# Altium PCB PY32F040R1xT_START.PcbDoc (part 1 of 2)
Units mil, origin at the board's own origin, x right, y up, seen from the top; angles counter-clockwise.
Board outline 1771.65 x 3925.12 mil, 2 copper layers (Top Layer, Bottom Layer), stack 21 mil thick; 156 components, 167 nets, 616 pads, 288 vias.
Unrouted connection lines stored in the file: 5.
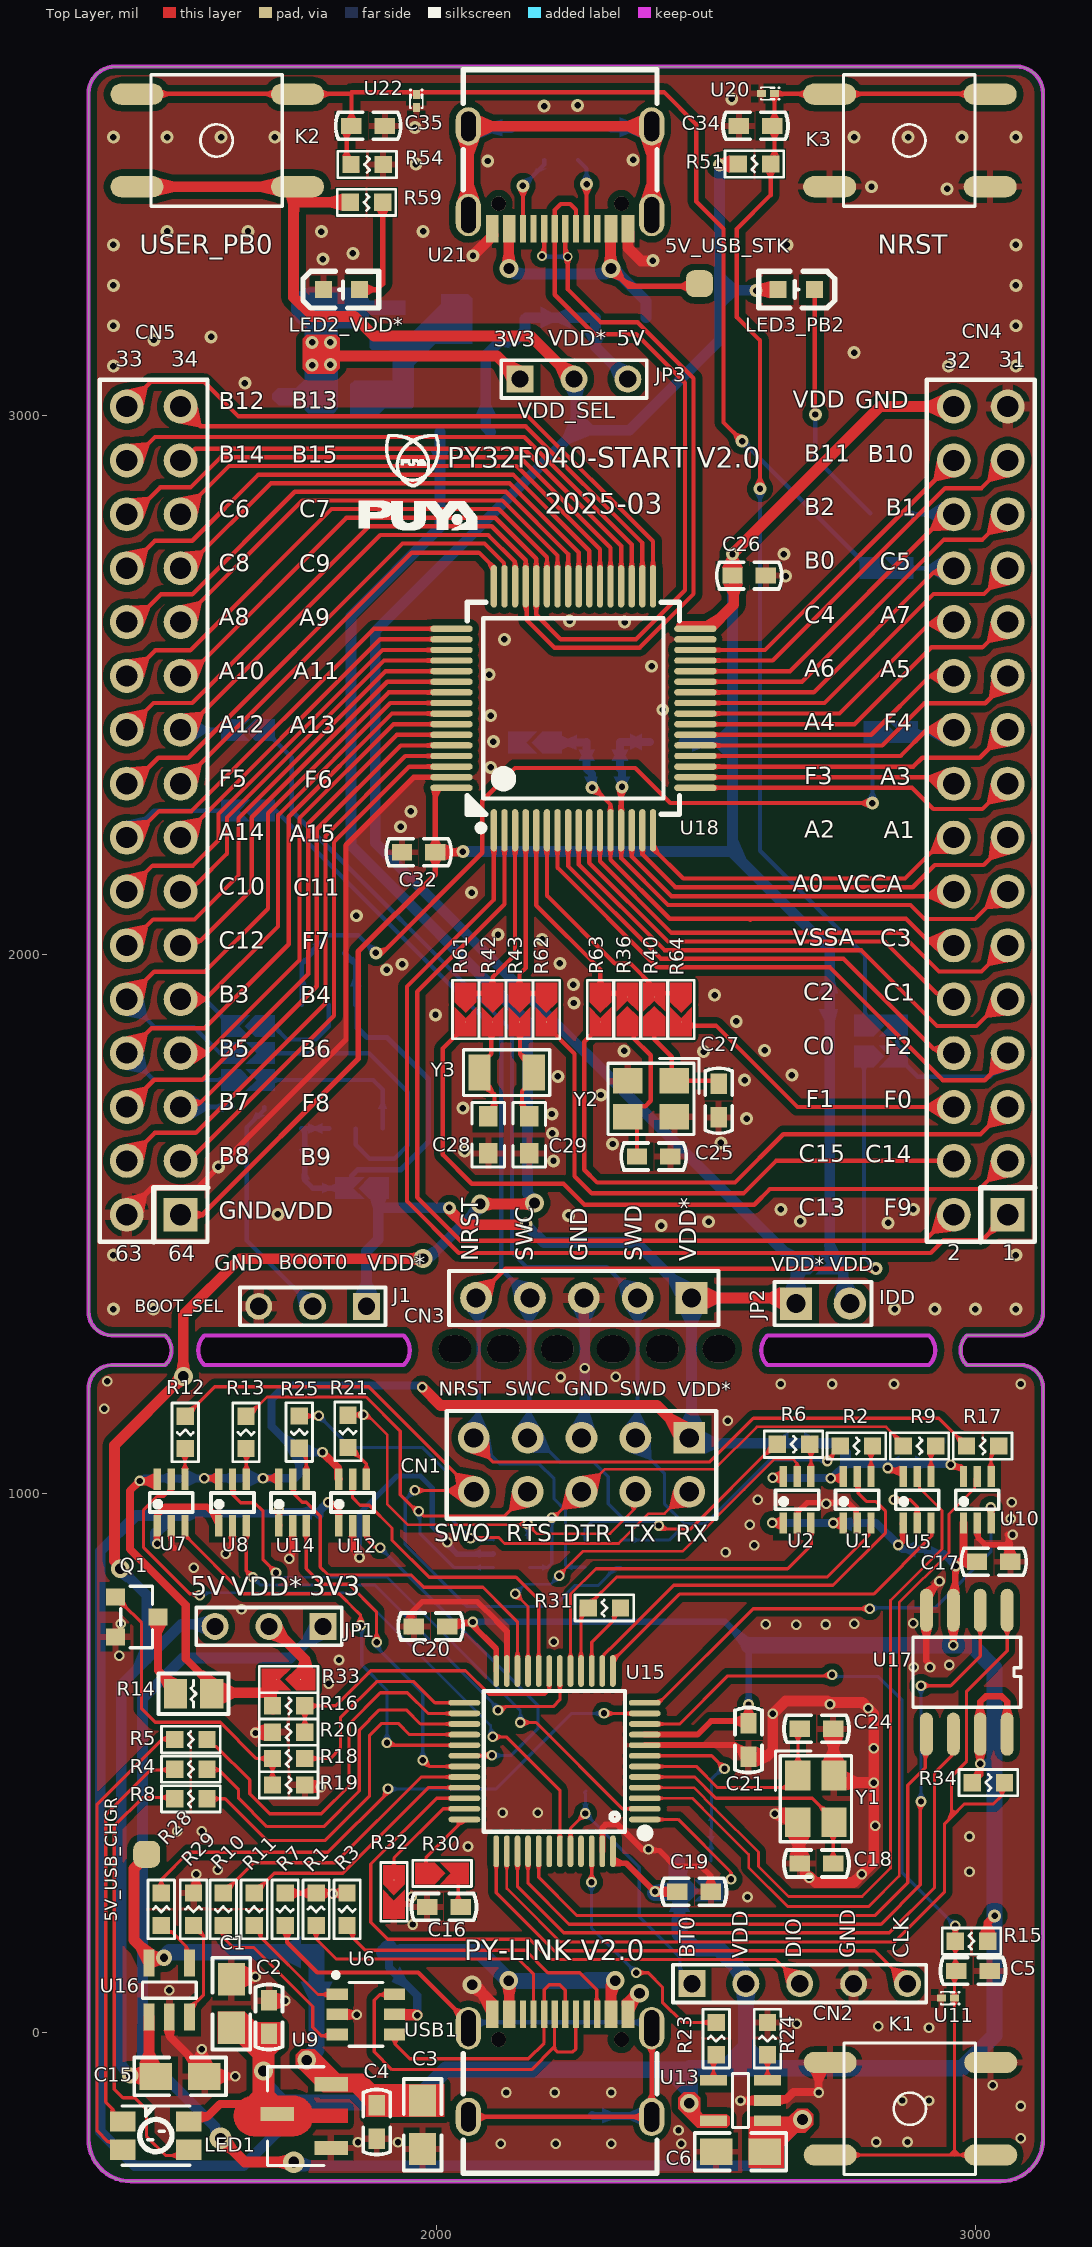
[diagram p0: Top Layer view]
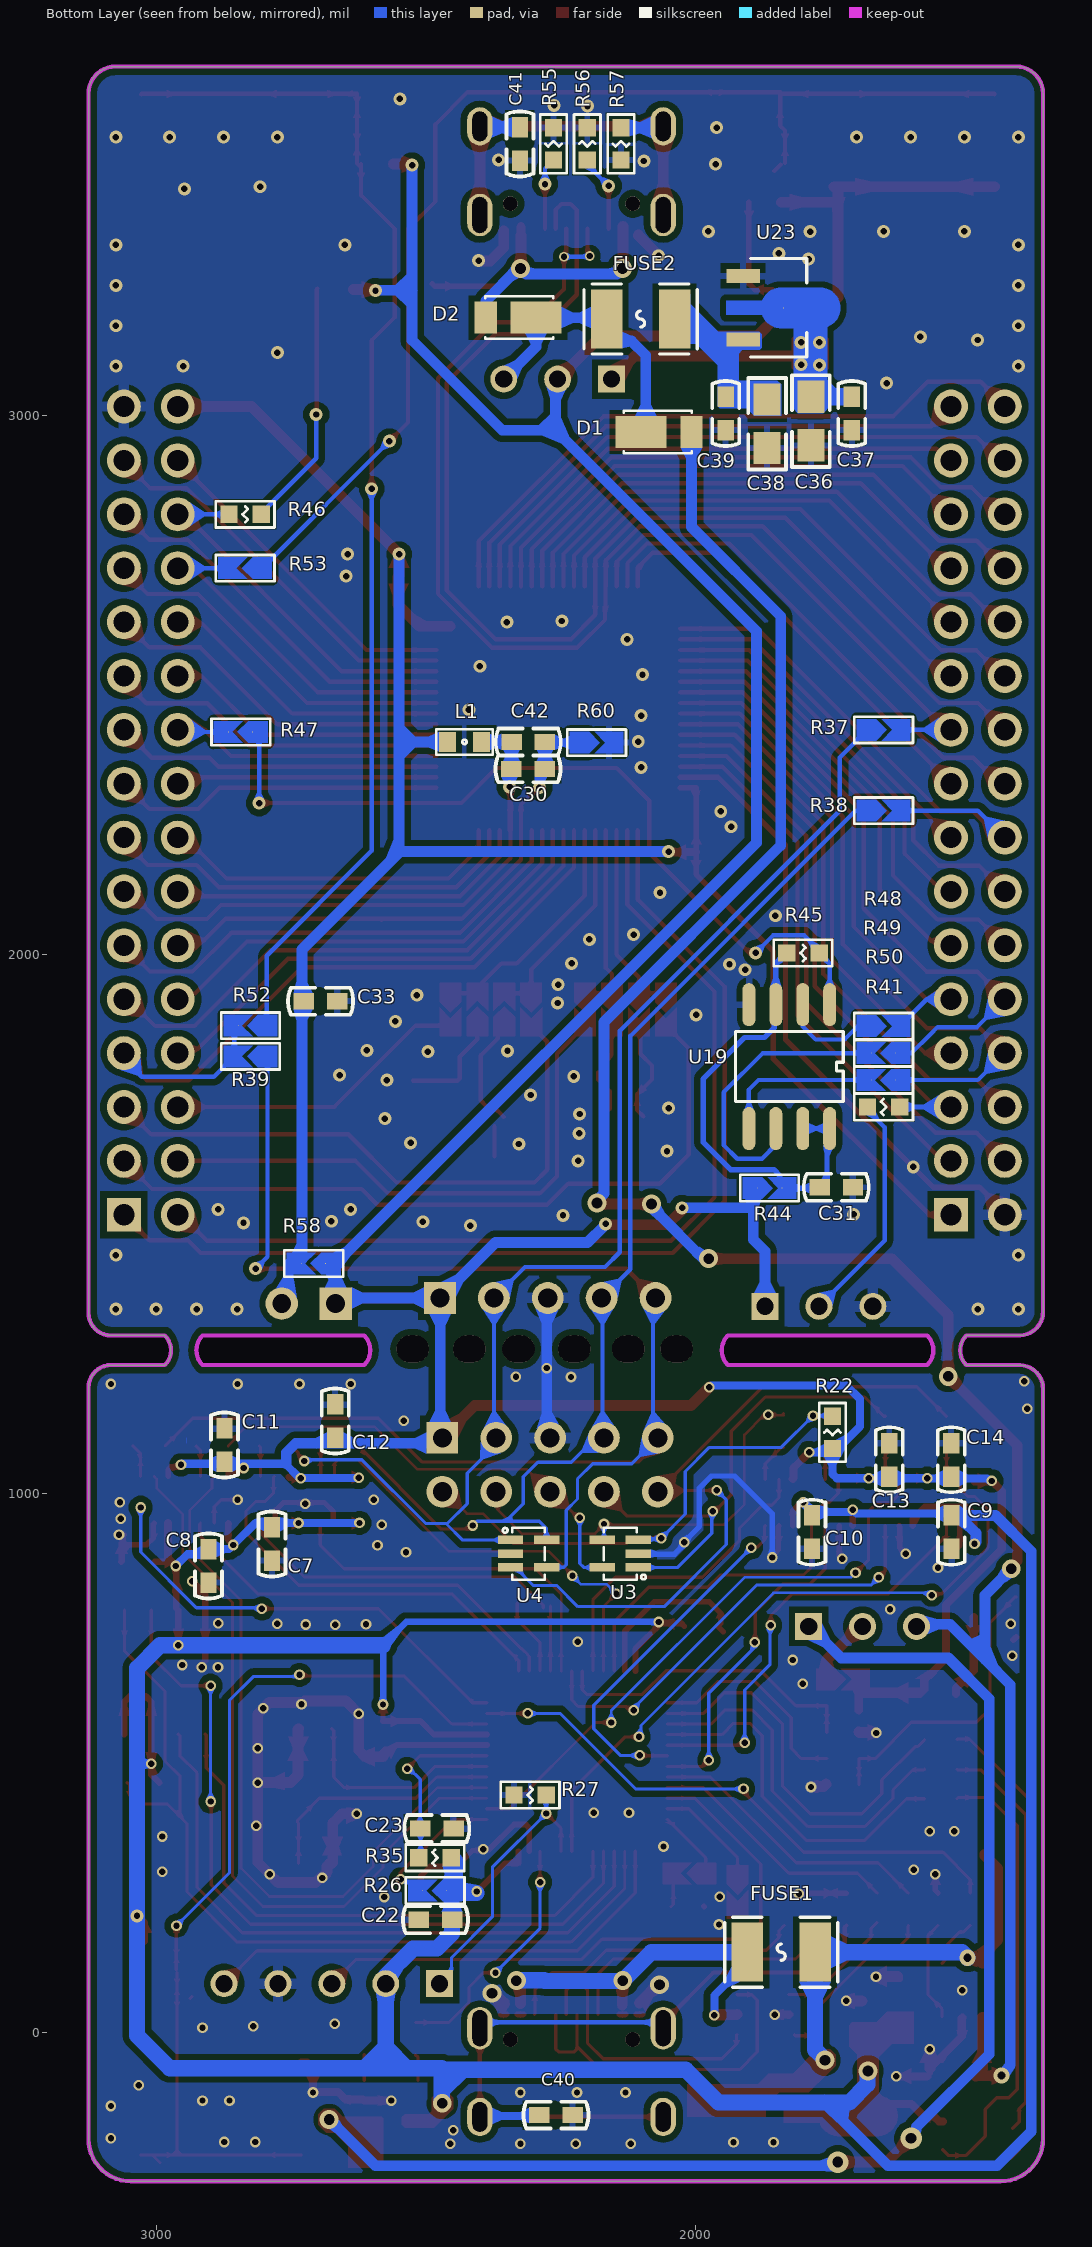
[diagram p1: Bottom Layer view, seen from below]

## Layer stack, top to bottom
Top Solder: solder mask 0.4, Solder Resist, Dk 3.5
Top Layer: signal copper 1.4
Dielectric 2: prepreg 2.8, Composite dielectric, Dk 4.1
Dielectric 1: prepreg 12.6, Composite dielectric, Dk 4.1
Dielectric 3: prepreg 2.8, Composite dielectric, Dk 4.1
Bottom Layer: signal copper 1.4
Bottom Solder: solder mask 0.4, Solder Resist, Dk 3.5

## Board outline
1354,-198.26 1354,1193 cw(c1397.75,1194.25) 1396.5,1238 1496.5,1238 ccw(c1469,1265.5) 1496.5,1293 1396.5,1293 cw(c1397.75,1336.75) 1354,1338 1354,3598.12 cw(c1404,3598.12) 1404,3648.12 3075.65,3648.12 cw(c3075.65,3598.12) 3125.65,3598.12 3125.65,1334.65 cw(c3084,1334.65) 3084,1293 2984,1293 ccw(c3011.5,1265.5) 2984,1238 3084,1238 cw(c3084,1196.35) 3125.65,1196.35 3125.65,-198.26 cw(c3046.91,-198.26) 3046.91,-277 1432.74,-277 cw(c1432.74,-198.26)
cut-out: 2614,1238 cw(c2641.5,1265.5) 2614,1293 2914,1293 cw(c2886.5,1265.5) 2914,1238
cut-out: 1569,1238 cw(c1596.5,1265.5) 1569,1293 1939,1293 cw(c1911.5,1265.5) 1939,1238
cut-out: 1569,1238 cw(c1596.5,1265.5) 1569,1293 1939,1293 cw(c1911.5,1265.5) 1939,1238 1919,1238
cut-out: 2614,1238 cw(c2641.5,1265.5) 2614,1293 2914,1293 cw(c2886.5,1265.5) 2914,1238

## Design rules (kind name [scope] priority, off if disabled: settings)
Clearance polygon [InPolygon] p1: gap=12 ignorepadtopadclearanceinfootprint=TRUE
Clearance [All] p2: gap=6 ignorepadtopadclearanceinfootprint=TRUE
HoleToHoleClearance [All] p1: gap=1 allowstackedmicrovias=TRUE
MinimumSolderMaskSliver [All] p1: minsoldermaskwidth=0
PlaneClearance [All] p1: clearance=8
PlaneConnect [All] p1: planeconnectstyle=Direct reliefexpansion=20 reliefentries=4 reliefconductorwidth=10 reliefairgap=10
PolygonConnect [All] p1: thpad.connectstyle=Relief thpad.reliefconductorwidth=20 thpad.reliefentries=4 thpad.polygonreliefangle="90 Angle" thpad.airgapwidth=10 smdpad.connectstyle=Relief smdpad.reliefconductorwidth=12 smdpad.reliefentries=4 smdpad.polygonreliefangle="90 Angle" smdpad.airgapwidth=10 via.connectstyle=Direct via.reliefconductorwidth=10 via.reliefentries=4 via.polygonreliefangle="90 Angle" via.airgapwidth=10
RoutingVias [All] p1: holewidth=28 width=50 viastyle="Through Hole" minholewidth=28 minwidth=50 maxholewidth=28 maxwidth=50
SilkToSilkClearance [All] p1: silktosilkclearance=0
SilkToSolderMaskClearance [IsPad] p1: minsilkscreentomaskgap=0 clearancetoexposedcopper=TRUE
SolderMaskExpansion [All] p1: expansion=4 istentingtop=FALSE
UnRoutedNet [All] p1: checkbadconnections=TRUE
Width [All] p1: maxlimit=100 minlimit=5 preferedwidth=8
23 further rules are at their usual default settings.

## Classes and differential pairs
component class PY32F040R1xT_START: 5V_USB_STK C25 C26 C27 C28 C29 C30 C31 C32 C33 C34 C35 C36 C37 C38 C39 C41 C42 CN3 CN4 CN5 D1 D2 FUSE2 "IDD Test" J1 JP2 JP3 K2 K3 L1 LED2_VDD* LED3_PB2 PF8 R36 R37 R38 R39 R40 R41 R42 R43 R44 R45 R46 R47 R48 R49 R50 R51 R52 R53 R54 R55 R56 R57 R58 R59 R60 R61 R62 R63 R64 ss U18 U19 U20 U21 U22 U23 Y2 Y3
component class PY32F403C1xT_LINK: 5V_USB_CHGR C1 C2 C3 C4 C5 C6 C7 C8 C9 C10 C11 C12 C13 C14 C15 C16 C17 C18 C19 C20 C21 C22 C23 C24 C40 CN1 CN2 FUSE1 JP1 K1 LED1 Q1 R1 R2 R3 R4 R5 R6 R7 R8 R9 R10 R11 R12 R13 R14 R15 R16 R17 R18 R19 R20 R21 R22 R23 R24 R25 R26 R27 R28 R29 R30 R31 R32 R33 R34 R35 ss U1 U2 U3 U4 U5 U6 U7 U8 U9 U10 U11 U12 U13 U14 U15 U16 U17 USB1 Y1

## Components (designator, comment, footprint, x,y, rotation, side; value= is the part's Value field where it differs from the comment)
5V_USB_CHGR "5V_USB_CHGR" TP_SIN 1462,330 r90 top
5V_USB_STK "5V_USB_STK" TP_SIN 2488,3245 r90 top
C1 "10uF" C0805 1619,53 r270 top
C2 "100nF" C0603 1689,28 r270 top
C3 "10uF" C0805 1974,-172 r90 top
C4 "100nF" C0603 1889,-167 r90 top
C5 "100nF" C0603 2995.51,113.75 r180 top
C6 "10uF" C0805 2564,-222 r0 top
C7 "100nF" C0603 2785,906 r90 bottom value=104
C8 "100nF" C0603 2902.9,865.3 r90 bottom value=104
C9 "100nF" C0603 1524.2,927.9 r90 bottom value=104
C10 "100nF" C0603 1783,927.9 r90 bottom value=104
C11 "100nF" C0603 2873.4,1089.6 r270 bottom value=104
C12 "100nF" C0603 2667.8,1134.1 r270 bottom value=104
C13 "100nF" C0603 1639.5,1062.2 r270 bottom value=104
C14 "100nF" C0603 1524.5,1062.2 r270 bottom value=104
C15 "10uF" C0805 1524,-82 r180 top
C16 "100nF" C0603 2013.59,232.5 r0 top
C17 "100nF" C0603 3034,873 r180 top value=104
C18 "22pF" C0603 2705.12,313 r0 top
C19 "100nF" C0603 2477.87,260.59 r180 top value=104
C20 "100nF" C0603 1989,753 r0 top value=104
C21 "100nF" C0603 2579.12,542 r90 top value=104
C22 "100nF" C0603 2481.74,208.58 r180 bottom value=104
C23 "100nF" C0603 2479.12,378 r0 bottom value=104
C24 "22pF" C0603 2705.12,563 r180 top
C25 "22pF" C0603 2403,1625 r180 top
C26 "100nF" C0603 2580.22,2703.24 r0 top
C27 "22pF" C0603 2523.67,1728.77 r90 top
C28 "22pF" 0603C 2096,1665.5 r270 top
C29 "22pF" 0603C 2172,1665.5 r90 top
C30 "100nF" C0603 2309.94,2344.58 r0 bottom
C31 "100nF/NC" C0603 1737.78,1568.07 r0 bottom value=104
C32 "100nF" C0603 1966.86,2189.8 r0 top
C33 "4.7uF" C0603 2694.86,1913.37 r0 bottom
C34 "100nF" C0603 2592,3538 r0 top
C35 "100nF" C0603 1873,3538 r180 top
C36 "10uF" C0805 1785,2990 r90 bottom
C37 "100nF" C0603 1709,3004 r90 bottom
C38 "10uF" C0805 1866,2985 r90 bottom
C39 "100nF" C0603 1943,3004 r90 bottom
C40 "4.7nF" C0603 2258,-154 r0 bottom
C41 "4.7nF" C0603 2325,3504.5 r90 bottom
C42 "1uF" C0603 2309.51,2394.65 r180 bottom
CN1 "2X5P" HDR2X5 2469,1103 r180 top
CN2 "CON5" CON5 2474,90 r0 top
CN3 "Header 5" HDR1X5 2473.26,1362.56 r180 top
CN4 "2X16P 2.54mm" HDR-TH_32P-P2.54-V-M-R2-C16-S2.54-3 3010,2267 r90 top
CN5 "2X16P 2.54mm" HDR-TH_32P-P2.54-V-M-R2-C16-S2.54-3 1475,2267 r90 top
D1 "DFLS130L-7" POWERDI-123_L2.8-W1.8-LS3.7-RD 2053.25,2970 r180 bottom
D2 "DFLS130L-7" POWERDI-123_L2.8-W1.8-LS3.7-RD 2341.75,3182 r0 bottom
FUSE1 "BSMD1206-050-6V" SDM1210P005TF 1843,170 r180 bottom locked
FUSE2 "SMD1210P005TF" SDM1210P005TF 2104,3201 r180 bottom
J1 "CON3" CON3 1870,1347.13 r180 top
JP1 "CON3" CON3 1789,753 r180 top
JP2 "CON2" CON2 2667,1352.13 r0 top
JP3 "CON3" CON3 2155,3068 r0 top
K1 "1TS002B-2600-5001_key" Switch 2877.55,-142 r0 top
K2 "1TS002B-2600-5001_key" Switch 1591,3511 r0 top locked
K3 "1TS002B-2600-5001_key" Switch 2876.55,3511 r0 top locked
L1 "BEAD" L0603 2427.79,2394.53 r180 bottom value=600R@100MHz
LED1 "MHPA3528RGBCT" LED-ARRAY-SMD_4P-L3.5-W2.8-TL 1479,-192 r0 top
LED2_VDD* "RED" 0603_LED 1838,3233 r0 top
LED3_PB2 "GREEN" 0603_LED 2653,3235 r180 top
Q1 "2302" SOT23 1443.37,770.4 r90 top value=SI2302
R1 "5.1K" R0603 1776.49,227.99 r270 top
R2 "27R" R0603 2779.21,1088 r180 top
R3 "5.1K" R0603 1834,228 r90 top
R4 "680R" R0603 1544,488 r0 top
R5 "680R" R0603 1544,543 r0 top
R6 "27R" R0603 2662.39,1091.1 r180 top
R7 "1M" R0603 1719,228 r90 top
R8 "680R" R0603 1544,433 r0 top
R9 "27R" R0603 2896.35,1088 r180 top
R10 "27R" R0603 1604,228 r90 top
R11 "27R" R0603 1661.5,228 r90 top
R12 "27R" R0603 1533.66,1113.08 r90 top
R13 "27R" R0603 1646.3,1113.1 r90 top
R14 "100R" R0805 1549,628 r0 top
R15 "10K" R0603 2992.76,168.85 r0 top
R16 "20K" R0603 1725.52,605.61 r180 top
R17 "27R" R0603 3013.49,1088 r180 top
R18 "680R" R0603 1725.53,507.78 r0 top
R19 "100K" R0603 1725.52,458.88 r180 top
R20 "10K" R0603 1725.53,556.69 r0 top
R21 "27R" R0603 1835.63,1115.11 r90 top
R22 "4.7K" R0603 1745,1113 r270 bottom
R23 "5.1K" R0603 2519,-12 r270 top
R24 "16K" R0603 2614,-12 r270 top
R25 "27R" R0603 1745.2,1113.7 r90 top
R26 "0R" JP2_SMD 2482.34,262.83 r180 bottom
R27 "10K" R0603 2306,440.08 r0 bottom
R28 "5.1K" R0603 1489,228 r270 top
R29 "16K" R0603 1549,228 r270 top
R30 "0R" JP2_SMD 2010.21,294.75 r180 top
R31 "680R" R0603 2311.46,787.37 r0 top
R32 "0R" JP2_SMD 1920.96,260.4 r90 top
R33 "0R" JP2_SMD 1725.52,654.52 r0 top
R34 "100K" R0603 3024,463 r180 top
R35 "100K" R0603 2482.6,323.62 r180 bottom
R36 "0R" JP2_SMD 2354,1898 r270 top
R37 "0R" JP2_SMD 1650,2417 r0 bottom
R38 "0R" JP2_SMD 1650,2267 r0 bottom
R39 "0R" JP2_SMD 2825,1811 r180 bottom
R40 "0R" JP2_SMD 2404,1898 r270 top
R41 "10K" R0603 1650,1717 r180 bottom
R42 "0R" JP2_SMD 2104,1898 r90 top
R43 "0R" JP2_SMD 2154,1898 r90 top
R44 "0R/NC" JP2_SMD 1861.72,1566.57 r0 bottom
R45 "100K/NC" R0603 1799.57,2002.7 r0 bottom
R46 "680R" R0603 2835,2817 r0 bottom
R47 "0R/NC" JP2_SMD 2843,2413 r180 bottom
R48 "0R/NC" JP2_SMD 1650,1867 r0 bottom
R49 "0R/NC" JP2_SMD 1650,1817 r180 bottom
R50 "0R/NC" JP2_SMD 1650,1767 r180 bottom
R51 "10K" R0603 2590,3467.24 r0 top
R52 "0R" JP2_SMD 2825,1868 r180 bottom
R53 "0R" JP2_SMD 2835,2717 r180 bottom
R54 "5.1K" R0603 1871,3466.26 r180 top
R55 "5.1K" R0603 2262.5,3504.5 r90 bottom
R56 "5.1K" R0603 2200,3504.5 r270 bottom
R57 "1M" R0603 2137.5,3504.5 r90 bottom
R58 "0R" JP2_SMD 2707.64,1426.61 r180 bottom
R59 "680R" R0603 1870,3396 r180 top
R60 "0R" JP2_SMD 2182.63,2393.15 r0 bottom
R61 "0R" JP2_SMD 2054,1898 r90 top
R62 "0R" JP2_SMD 2204,1898 r90 top
R63 "0R" JP2_SMD 2304,1898 r90 top
R64 "0R" JP2_SMD 2454,1898 r90 top
U1 "74LVC1T45DW" SOT363 2780.64,988 r0 top
U2 "74LVC1T45DW" SOT363 2669.21,988 r0 top
U3 "ESD_6V1" ESD_SOT323-5L 2139,888 r90 bottom value=ESDALC6V1W5
U4 "ESD_6V1" ESD_SOT323-5L 2309,888 r270 bottom value=ESDALC6V1W5
U5 "74LVC1T45DW" SOT363 2892.06,988 r0 top locked
U6 "USBLC6-2SC6" SOT23-6 1869,33 r90 top
U7 "74LVC1T45DW" SOT363 1507.55,983 r0 top locked
U8 "74LVC1T45DW" SOT363 1621.26,983 r0 top
U9 "LM1117-3.3" LM1117-3.3#1 1804.38,-214.9 r0 top
U10 "74LVC1T45DW" SOT363 3003.49,988 r0 top
U11 "ESD-TRANSIL" ESD_ST0201 2949,63 r180 top value=ESDALC6V1-1U2
U12 "74LVC1T45DW" SOT363 1844.12,983 r0 top
U13 "MT9700" SOT23-5 2564,-127 r90 top
U14 "74LVC1T45DW" SOT363 1732.69,983 r0 top
U15 "PY32F403C1xT" LQFP-48_L7.0-W7.0-P0.50-LS9.0-BL 2219,503 r90 top locked
U16 "MT9700" SOT23-5 1504,78 r0 top
U17 "P25Q64H" SOP-8P 2984,668 r180 top value=SST25VF020B
U18 "PY32F072x" LQFP-64_L10.0-W10.0-P0.50-LS12.0-BL 2254,2457 r0 top locked
U19 "P25Q64H/NC" SOP-8P 1825,1792 r0 bottom value=SST25VF020B
U20 "ESD-TRANSIL" ESD_ST0201 2615,3598 r180 top value=ESDALC6V1-1U2
U21 "KH-TYPE-C-16P" USB-C-SMD_KH-TYPE-C-16P 2229.2,3442 r180 top locked
U22 "ESD-TRANSIL" ESD_ST0201 1962.34,3583.99 r270 top value=ESDALC6V1-1U2
U23 "LM1117-3.3" LM1117-3.3#2 1910.84,3259.4 r0 bottom
USB1 "KH-TYPE-C-16P" USB-C-SMD_KH-TYPE-C-16P 2229.2,-62.19 r0 top locked
Y1 "24MHz" CRYSTAL-SMD_4P-L3.2-W2.5-BL 2704.12,433 r270 top
Y2 "24MHz" CRYSTAL-SMD_4P-L3.2-W2.5-BL 2398,1732 r180 top
Y3 "32.768KHz" CRYSTAL-SMD_L3.2-W1.5-1 2130,1781 r180 top value=X503225MSB2GI

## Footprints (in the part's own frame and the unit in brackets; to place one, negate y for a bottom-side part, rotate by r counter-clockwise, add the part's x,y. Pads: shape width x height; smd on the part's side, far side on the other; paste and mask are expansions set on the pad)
0603_LED [mil]
  rect 31.5x31.5 smd: 1(19,1) 2(-48,1)
  silkscreen extent -86,-33 55,35
0603C [mil]
  rect 38x35 smd: 1(-34.5,0) 2(34.5,0)
  silkscreen extent -60,-30 60,30, body extent -31,-16 32,16, height 12
C0603 [mil]
  rect 38x30 smd: 1(-31,0) 2(31,0)
  silkscreen extent -60,-25 60,25
C0805 [mil]
  rect 60x50 smd: 1(-45,0) 2(45,0)
  silkscreen extent -85,-35 85,35
CON2 [mil]
  rect 60x60 hole 35: 1(0,0)
  round 60 hole 35: 2(100,0)
  silkscreen extent -40,-40 140,40
CON3 [mil]
  rect 50x50 hole 32: 1(0,0)
  round 50 hole 32: 2(100,0) 3(200,0)
  silkscreen extent -35,-35 235,35
CON5 [mil]
  rect 50x50 hole 32: 1(0,0)
  round 50 hole 32: 2(100,0) 3(200,0) 4(300,0) 5(400,0)
  silkscreen extent -35,-35 435,35
CRYSTAL-SMD_4P-L3.2-W2.5-BL [mm]
  rect 1.4x1.2 smd: 1(-1.1,-0.85) 2(1.1,-0.85) 3(1.1,0.85) 4(-1.1,0.85)
  silkscreen extent -2.26,-1.91 2.03,1.68
CRYSTAL-SMD_L3.2-W1.5-1 [mm]
  rect 1.05x1.7 smd: 1(-1.275,0) 2(1.275,0)
  silkscreen extent -2.03,-1.08 2.03,1.08
ESD_SOT323-5L [mm]
  rect 0.4x1.2 smd mask+0.05: 1(-0.65,-0.85) 2(0,-0.85) 3(0.65,-0.85) 4(0.65,0.85) 5(-0.65,0.85)
  silkscreen extent -1.23,-1.21 1.23,0.77, body extent -1.15,-1.05 1.15,1.05, height 1.1
ESD_ST0201 [mm]
  rect 0.425x0.33 smd mask+0.05: 1(-0.312,0) 2(0.312,0)
  silkscreen extent -0.55,-0.3 0.33,0.3, body extent -0.34,-0.18 0.34,0.18, height 0.34
HDR1X5 [mm] "Connector; Header; 5 Position"
  rect 1.5x1.5 hole 0.9: 1(0,0)
  round 1.5 hole 0.9: 2(2.54,0) 3(5.08,0) 4(7.62,0) 5(10.16,0)
  silkscreen extent -1.27,-1.27 11.43,1.27
HDR2X5 [mm] "Connector; Header; 4x2 Position"
  rect 1.5x1.5 hole 0.9: 1(0,0)
  round 1.5 hole 0.9: 2(0,2.54) 3(2.54,0) 4(2.54,2.54) 5(5.08,0) 6(5.08,2.54) 7(7.62,0) 8(7.62,2.54) 9(10.16,0) 10(10.16,2.54)
  silkscreen extent -1.27,-1.27 11.43,3.81
HDR-TH_32P-P2.54-V-M-R2-C16-S2.54-3 [mm]
  rect 1.6x1.6 hole 1: 1(-19.05,-1.27)
  round 1.6 hole 1: 2(-19.05,1.27) 3(-16.51,-1.27) 4(-16.51,1.27) 5(-13.97,-1.27) 6(-13.97,1.27) 7(-11.43,-1.27) 8(-11.43,1.27) 9(-8.89,-1.27) 10(-8.89,1.27) 11(-6.35,-1.27) 12(-6.35,1.27) 13(-3.81,-1.27) 14(-3.81,1.27) 15(-1.27,-1.27) 16(-1.27,1.27) 17(1.27,-1.27) 18(1.27,1.27) 19(3.81,-1.27) 20(3.81,1.27) 21(6.35,-1.27) 22(6.35,1.27) 23(8.89,-1.27) 24(8.89,1.27) 25(11.43,-1.27) 26(11.43,1.27) 27(13.97,-1.27) 28(13.97,1.27) 29(16.51,-1.27) 30(16.51,1.27) 31(19.05,-1.27) 32(19.05,1.27)
  silkscreen extent -20.32,-2.54 20.32,2.54
JP2_SMD [mil]
  round 1 smd: 1(21.75,0) 2(-23.03,0.03)
  Top Layer region: -49.77,20.03 -49.77,20.03 3.72,20.03 -16.28,0.03 3.72,-19.98 -49.78,-19.98 -49.78,-19.98
  Top Layer region: -6.25,0 13.75,20 49.75,20 49.75,-20 49.75,-20 13.75,-20
  silkscreen extent -55,-25 54,25
L0603 [mm]
  rect 0.8x0.95 smd mask+0.05: 1(-0.8,0) 2(0.8,0)
  silkscreen extent -1.33,-0.6 1.33,0.6, body extent -0.87,-0.47 0.87,0.47, height 0.95
LED-ARRAY-SMD_4P-L3.5-W2.8-TL [mm]
  rect 1.2x0.95 smd: 1(1.55,0.665) 2(1.55,-0.665) 3(-1.55,-0.665) 4(-1.55,0.665)
  silkscreen extent -1.6,-1.4 1.6,1.4
LM1117-3.3#1 [mm]
  rect 1.575x0.672 smd: 1(0,0) 2(-2.55,1.598) 3(0,3)
  Top Layer region: -3.64,2.459 -1.785,2.459 -1.741,2.458 -1.696,2.455 -1.652,2.449 -1.608,2.442 -1.565,2.433 -1.522,2.421 -1.479,2.408 -1.437,2.393 -1.396,2.375 -1.356,2.356 -1.317,2.335 -1.279,2.312 -1.241,2.288 -1.206,2.261 -1.171,2.233 -1.138,2.204 -1.106,2.173 -1.075,2.14 -1.047,2.106 -1.019,2.071 -0.994,2.034 -0.97,1.996 -0.948,1.958 -0.928,1.918 -0.91,1.839 0.788,1.839 0.788,1.179 -0.91,1.179 -0.928,1.099 -0.948,1.06 -0.97,1.021 -0.994,0.983 -1.019,0.947 -1.047,0.911 -1.075,0.877 -1.106,0.845 -1.138,0.814 -1.171,0.784 -1.206,0.756 -1.241,0.73 -1.279,0.705 -1.317,0.682 -1.356,0.661 -1.396,0.642 -1.437,0.625 -1.479,0.609 -1.522,0.596 -1.565,0.585 -1.608,0.575 -1.652,0.568 -1.696,0.563 -1.741,0.56 -1.785,0.559 -3.64,0.559 -3.684,0.56 -3.728,0.563 -3.773,0.568 -3.817,0.575 -3.86,0.585 -3.903,0.596 -3.946,0.609 -3.988,0.625 -4.029,0.642 -4.069,0.661 -4.108,0.682 -4.146,0.705 -4.183,0.73 -4.219,0.756 -4.254,0.784 -4.287,0.814 -4.319,0.845 -4.349,0.877 -4.378,0.911 -4.405,0.947 -4.431,0.983 -4.455,1.021 -4.477,1.06 -4.497,1.099 -4.515,1.14 -4.531,1.181 -4.546,1.224 -4.558,1.266 -4.568,1.31 -4.577,1.353 -4.583,1.398 -4.587,1.442 -4.589,1.486 -4.589,1.531 -4.587,1.575 -4.583,1.62 -4.577,1.664 -4.568,1.708 -4.558,1.751 -4.546,1.794 -4.531,1.836 -4.515,1.877 -4.497,1.918 -4.477,1.958 -4.455,1.996 -4.431,2.034 -4.405,2.071 -4.378,2.106 -4.349,2.14 -4.319,2.173 -4.287,2.204 -4.254,2.233 -4.219,2.261 -4.183,2.288 -4.146,2.312 -4.108,2.335 -4.069,2.356 -4.029,2.375 -3.988,2.393 -3.946,2.408 -3.903,2.421 -3.86,2.433 -3.817,2.442 -3.773,2.449 -3.728,2.455 -3.684,2.458
  silkscreen extent -3.01,-0.83 -0.35,3.83
LM1117-3.3#2 [mm]
  rect 1.575x0.672 smd: 1(0,0) 3(0,3)
  round 0.025 smd: 2(-1.901,1.509)
  Top Layer region: -3.64,2.459 -1.785,2.459 -1.741,2.458 -1.696,2.455 -1.652,2.449 -1.608,2.442 -1.565,2.433 -1.522,2.421 -1.479,2.408 -1.437,2.393 -1.396,2.375 -1.356,2.356 -1.317,2.335 -1.279,2.312 -1.241,2.288 -1.206,2.261 -1.171,2.233 -1.138,2.204 -1.106,2.173 -1.075,2.14 -1.047,2.106 -1.019,2.071 -0.994,2.034 -0.97,1.996 -0.948,1.958 -0.928,1.918 -0.91,1.839 0.788,1.839 0.788,1.179 -0.91,1.179 -0.928,1.099 -0.948,1.06 -0.97,1.021 -0.994,0.983 -1.019,0.947 -1.047,0.911 -1.075,0.877 -1.106,0.845 -1.138,0.814 -1.171,0.784 -1.206,0.756 -1.241,0.73 -1.279,0.705 -1.317,0.682 -1.356,0.661 -1.396,0.642 -1.437,0.625 -1.479,0.609 -1.522,0.596 -1.565,0.585 -1.608,0.575 -1.652,0.568 -1.696,0.563 -1.741,0.56 -1.785,0.559 -3.64,0.559 -3.684,0.56 -3.728,0.563 -3.773,0.568 -3.817,0.575 -3.86,0.585 -3.903,0.596 -3.946,0.609 -3.988,0.625 -4.029,0.642 -4.069,0.661 -4.108,0.682 -4.146,0.705 -4.183,0.73 -4.219,0.756 -4.254,0.784 -4.287,0.814 -4.319,0.845 -4.349,0.877 -4.378,0.911 -4.405,0.947 -4.431,0.983 -4.455,1.021 -4.477,1.06 -4.497,1.099 -4.515,1.14 -4.531,1.181 -4.546,1.224 -4.558,1.266 -4.568,1.31 -4.577,1.353 -4.583,1.398 -4.587,1.442 -4.589,1.486 -4.589,1.531 -4.587,1.575 -4.583,1.62 -4.577,1.664 -4.568,1.708 -4.558,1.751 -4.546,1.794 -4.531,1.836 -4.515,1.877 -4.497,1.918 -4.477,1.958 -4.455,1.996 -4.431,2.034 -4.405,2.071 -4.378,2.106 -4.349,2.14 -4.319,2.173 -4.287,2.204 -4.254,2.233 -4.219,2.261 -4.183,2.288 -4.146,2.312 -4.108,2.335 -4.069,2.356 -4.029,2.375 -3.988,2.393 -3.946,2.408 -3.903,2.421 -3.86,2.433 -3.817,2.442 -3.773,2.449 -3.728,2.455 -3.684,2.458
  silkscreen extent -3.01,-0.83 -0.35,3.83
LQFP-48_L7.0-W7.0-P0.50-LS9.0-BL [mm]
  oval 0.27x1.5 smd mask+0.05: 1(-2.75,-4.25) 2(-2.25,-4.25) 3(-1.75,-4.25) 4(-1.25,-4.25) 5(-0.75,-4.25) 6(-0.25,-4.25) 7(0.25,-4.25) 8(0.75,-4.25) 9(1.25,-4.25) 10(1.75,-4.25) 11(2.25,-4.25) 12(2.75,-4.25) 25(2.75,4.25) 26(2.25,4.25) 27(1.75,4.25) 28(1.25,4.25) 29(0.75,4.25) 30(0.25,4.25) 31(-0.25,4.25) 32(-0.75,4.25) 33(-1.25,4.25) 34(-1.75,4.25) 35(-2.25,4.25) 36(-2.75,4.25)
  oval 1.5x0.27 smd mask+0.05: 13(4.25,-2.75) 14(4.25,-2.25) 15(4.25,-1.75) 16(4.25,-1.25) 17(4.25,-0.75) 18(4.25,-0.25) 19(4.25,0.25) 20(4.25,0.75) 21(4.25,1.25) 22(4.25,1.75) 23(4.25,2.25) 24(4.25,2.75) 37(-4.25,2.75) 38(-4.25,2.25) 39(-4.25,1.75) 40(-4.25,1.25) 41(-4.25,0.75) 42(-4.25,0.25) 43(-4.25,-0.25) 44(-4.25,-0.75) 45(-4.25,-1.25) 46(-4.25,-1.75) 47(-4.25,-2.25) 48(-4.25,-2.75)
  silkscreen extent -3.59,-4.46 3.3,3.34
LQFP-64_L10.0-W10.0-P0.50-LS12.0-BL [mm]
  oval 0.3x2 smd: 1(-3.75,-5.75) 2(-3.25,-5.75) 3(-2.75,-5.75) 4(-2.25,-5.75) 5(-1.75,-5.75) 6(-1.25,-5.75) 7(-0.75,-5.75) 8(-0.25,-5.75) 9(0.25,-5.75) 10(0.75,-5.75) 11(1.25,-5.75) 12(1.75,-5.75) 13(2.25,-5.75) 14(2.75,-5.75) 15(3.25,-5.75) 16(3.75,-5.75) 33(3.75,5.75) 34(3.25,5.75) 35(2.75,5.75) 36(2.25,5.75) 37(1.75,5.75) 38(1.25,5.75) 39(0.75,5.75) 40(0.25,5.75) 41(-0.25,5.75) 42(-0.75,5.75) 43(-1.25,5.75) 44(-1.75,5.75) 45(-2.25,5.75) 46(-2.75,5.75) 47(-3.25,5.75) 48(-3.75,5.75)
  oval 2x0.3 smd: 17(5.75,-3.75) 18(5.75,-3.25) 19(5.75,-2.75) 20(5.75,-2.25) 21(5.75,-1.75) 22(5.75,-1.25) 23(5.75,-0.75) 24(5.75,-0.25) 25(5.75,0.25) 26(5.75,0.75) 27(5.75,1.25) 28(5.75,1.75) 29(5.75,2.25) 30(5.75,2.75) 31(5.75,3.25) 32(5.75,3.75) 49(-5.75,3.75) 50(-5.75,3.25) 51(-5.75,2.75) 52(-5.75,2.25) 53(-5.75,1.75) 54(-5.75,1.25) 55(-5.75,0.75) 56(-5.75,0.25) 57(-5.75,-0.25) 58(-5.75,-0.75) 59(-5.75,-1.25) 60(-5.75,-1.75) 61(-5.75,-2.25) 62(-5.75,-2.75) 63(-5.75,-3.25) 64(-5.75,-3.75)
  silkscreen extent -5,-5.79 5,5
POWERDI-123_L2.8-W1.8-LS3.7-RD [mm]
  rect 2.4x1.5 smd: 1(-1.187,0)
  rect 1.05x1.5 smd: 2(1.187,0)
  silkscreen extent -2,-1 1.2,1
R0603 [mil]
  rect 32x32 smd: 1(-30,0) 2(30,0)
  silkscreen extent -55,-24 54,25
R0805 [mm]
  rect 1.1x1.4 smd: 1(-0.85,0) 2(0.85,0)
  silkscreen extent -1.65,-0.95 1.65,0.95
SDM1210P005TF [mm]
  rect 1.485x2.781 smd: 1(-1.524,-0.549) 2(1.676,-0.549)
  silkscreen extent -2.59,-2.2 2.74,1.1
SOP-8P [mil]
  oval 24x80 smd: 1(-75,-115) 2(-25,-115) 3(25,-115) 4(75,-115) 5(75,115) 6(25,115) 7(-25,115) 8(-75,115)
  silkscreen extent -100,-65 100,65
SOT23 [mm]
  rect 0.8x0.9 smd: 1(0.95,1) 2(-0.95,1) 3(0,-1)
  silkscreen extent -1.45,-0.75 1.45,0.75
SOT23-5 [mil]
  rect 20x50 smd: 1(-37.5,-50) 2(0,-50) 3(37.5,-50) 4(37.5,50) 5(-37.5,50)
  silkscreen extent -50,-15 50,15
SOT23-6 [mm]
  rect 0.55x1 smd: 1(0.95,1.35) 2(0,1.35) 3(-0.95,1.35) 4(-0.95,-1.35) 5(0,-1.35) 6(0.95,-1.35)
  silkscreen extent -1.5,-0.8 1.96,1.52
SOT363 [mm]
  rect 0.35x1 smd: 1(-0.65,-1.1) 2(0,-1.1) 3(0.65,-1.1) 4(0.65,1.1) 5(0,1.1) 6(-0.65,1.1)
  silkscreen extent -1.02,-0.45 1.02,0.45, body extent -1,-1.1 1,1.16, height 1
Switch [mm]
  oval 2.5x1 smd: 1(-3.734,2.177) 1(3.835,2.177) 2(-3.734,-2.184) 2(3.835,-2.184)
  silkscreen extent -3.08,-3.1 3.12,3.09, body extent -4.48,-3 4.52,3, height 8.95
TP_SIN [mil]
  rrect60% 50x50 smd: 1(0,0)
USB-C-SMD_KH-TYPE-C-16P [mm]
  oval 1.2x2 hole 0.7 slot 1.7 at 90 deg: 1(-4.32,1.765) 2(4.32,1.765)
  oval 1.2x1.8 hole 0.7 slot 1.4 at 90 deg: 3(-4.32,-2.415) 4(4.32,-2.415)
  rect 0.3x1.3 smd: A1(-3.35,2.415) A4(-2.55,2.415) A5(-1.25,2.415) A6(-0.25,2.415) A7(0.25,2.415) A8(1.25,2.415) A9(2.55,2.415) A12(3.35,2.415) B1(3.05,2.415) B4(2.25,2.415) B5(1.75,2.415) B6(0.75,2.415) B7(-0.75,2.415) B8(-1.75,2.415) B9(-2.25,2.415) B12(-3.05,2.415)
  round 0.7 hole 0.7 unplated: ""(-2.89,1.235) ""(2.89,1.235)
  silkscreen extent -4.57,-5.08 4.57,0.57

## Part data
5V_USB_CHGR 5V_USB_STK: library part TP_SIN
C1 C3 C6 C15 C36 C38: library part C0805
C2 C4 C5 C16 C18 C24 C25 C26 C27 C30 C32 C33 C34 C35 C37 C39 C40 C41 C42: library part C0603
C7 C8 C9 C10 C11 C12 C13 C14 C17 C19 C20 C21 C22 C23 C31: library part 贴片高压陶瓷电容, "Capacitor (Semiconductor SIM Model)"
C28 C29: library part Cap, "Capacitor"
CN1: Color=黑色, Current Rating (Max)=-, JLCPCB Part Class="Extended Part", LCSC Part Name="间距:2.54mm 2x5P 直插 方针", Manufacturer=XFCN(兴飞), Manufacturer Part=PZ254V-12-10P, Operating Temperature Range=-40℃~+105℃
CN3: "Header, 5-Pin"
CN4 CN5: Color=黑色, Current Rating (Max)=3A, JLCPCB Part Class="Extended Part", LCSC Part Name="2x16P 间距:2.54mm 方针", Manufacturer="XKB Connection(中国星坤)", Manufacturer Part=X6522WV-2x16H-C60D30-E80, Operating Temperature Range=-40℃~+105℃, Soldering Temperature(Max)=260℃, Voltage Rating (Max)=250V
D1 D2: Average Rectified Current (Io)=1A, Forward Voltage (Vf@If)=310mV@1A, JLCPCB Part Class="Extended Part", LCSC Part Name="电压:30V 电流:1A", Manufacturer=DIODES(美台), Reverse Voltage (Vr)=30V
FUSE1: library part SMD1210P005TF, "https://item.szlcsc.com/947797.html?fromZone=s_s__%25226V%2520500mA%2522"
JP2: library part CON2_DIP
JP3: library part JP3
K1 K2 K3: BOM_JLCPCB Part Class="Extended Part", BOM_Manufacturer=HYP, BOM_Manufacturer Part=1TS002B-2600-5001_KEY
L1: "SMD Chip ferrite bead, 600R@100MHz +/-25%, 350mA, 500mohm DC, 0603, T=0.8mm", Manufacturer=TAI-TECH, Manufacturer_Part_Number=FCM1608KF-601T03
LED1: JLCPCB Part Class=扩展库, LCSC Part Name=RGB三色, Manufacturer=MEIHUA(美华)
LED2_VDD* LED3_PB2: library part PDI-E803_Dup1
Q1: library part "MOSFET N", "MOSFET N"
R1 R2 R3 R4 R5 R6 R7 R8 R9 R10 R11 R12 R13 R15 R16 R17 R18 R19 R20 R21 R22 R23 R24 R25 R26 R27 R28 R29 R30 R31 R32 R33 R34 R35 R36 R37 R38 R39 R40 R41 R42 R43 R44 R45 R46 R47 R48 R49 R50 R51 R52 R53 R54 R55 R56 R57 R58 R59 R60 R61 R62 R63 R64: library part R0603
R14: library part R0805
U3 U4: library part ESDALC6V1W5, "Dual Transil array for ESD protection", Manufacturer=STMICROELECTRONICS
U11 U20 U22: "ESD protection 6V1", Manufacturer=STMICROELECTRONICS, Manufacturer_Part_Number=ESDALC6V1-1U2
U15: "LQFP48", BOM_Manufacturer=PUYA(普冉)
U17 U19: library part SST25VF010, "SST25VF010"
U18: BOM_JLCPCB Part Class="Extended Part", BOM_Manufacturer=ST, BOM_Manufacturer Part=STM32F103VCT6
U21 USB1: BOM_JLCPCB Part Class="Extended Part", BOM_Manufacturer="Shenzhen Kinghelm Elec"
Y1 Y2: library part ABM8AIG-24.000MHZ-82Z-T, "±20ppm , 12.5pF , T_use: -40°C~125°C", Equivalent Series Resistance (ESR)=50Ω, External load capacitor=8pF, Frequency Stability(Full temperature range)=±50ppm, JLCPCB Part Class="Extended Part", LCSC Part Name="24MHz ±20ppm 8pF", Manufacturer=ABRACON, Normal temperature Frequency Tolerance=±20ppm, Operating Temperature=-40℃~+125℃
Y3: library part CRYSTAL_1, "Crystal"

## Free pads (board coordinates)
  oval 60x50 hole 50 slot 60 at 0 deg unplated: 1(2034,1268) 1(2124,1268) 1(2224,1268) 1(2327.55,1268) 1(2419,1268) 1(2524,1268)

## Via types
v1: diameter 24, hole 12, Top Layer to Bottom Layer, tented both sides, 117 vias
v2: diameter 19.68, hole 11.81, Top Layer to Bottom Layer, tented both sides, 109 vias
v3: diameter 19.68, hole 11.81, Top Layer to Bottom Layer, 41 vias
v4: diameter 35, hole 20, Top Layer to Bottom Layer, tented both sides, 15 vias
v5: diameter 17.72, hole 11.81, Top Layer to Bottom Layer, tented both sides, 2 vias
v6: diameter 30, hole 15, Top Layer to Bottom Layer, tented both sides, 2 vias
v7: diameter 40, hole 20, Top Layer to Bottom Layer, tented both sides, 2 vias

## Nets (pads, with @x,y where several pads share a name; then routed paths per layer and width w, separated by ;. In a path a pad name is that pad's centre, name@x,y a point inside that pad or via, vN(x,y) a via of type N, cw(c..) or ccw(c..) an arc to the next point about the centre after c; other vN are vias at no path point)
3.3V_OUT: C36.2 C37.2 JP3.1 U23.2 | length 402.8
  Top Layer w20: 1770,3111 2112,3111 JP3.1@2155,3068
  other v1: 1769,3094 1803,3095 1769,3136 1803,3136
3.3V_OUT_EN: R23.1 U15.46 | length 463.4
  Top Layer w6: v2(2287.49,278.09) 2287.9,278.49 U15.46@2287.9,335.68 ; v2(2370.39,110.21) 2392.84,110.21 2419.25,83.8 2419.25,55.38 2456.62,18 R23.1@2519,18
  Bottom Layer w6: v2(2287.49,278.09) 2287.49,193.11 v2(2370.39,110.21)
3V3_PYLK: C1.2 C2.2 C7.2 C8.2 C9.2 C10.2 C17.2 C19.2 C20.2 C21.2 C22.2 CN2.2 LED1.1 R15.2 R26.1 R34.2 R35.2 U1.1 U2.1 U5.1 U7.1 U8.1 U9.2 U10.1 U12.1 U13.5 U14.1 U15.9 U15.24 U15.48 U17.3 U17.7 U17.8 | length 8006.2
  Top Layer w10: v2(1799.16,983.63) 1803.42,983.63 1818.53,968.52 U12.1@1818.53,939.69 ; C20.2@2020,753 C20.2@2024.66,757.66 ; C21.2@2579,577.12 v2(2579,608)
  Top Layer w11: v2@2064,758 2110.73,711.27 U15.24@2110.73,670.32 ; U15.48@2327.27,335.68 2327.27,313.61 2327.45,313.42 2352.23,313.42 2407.65,258 v2@2409.12,258 ; U15.9@2386.32,552.21 2484.39,552.21 2509.3,577.12 C21.2@2579,577.12
  Top Layer w12: v3(1481.35,906.66) 1481.96,907.27 U7.1@1481.96,939.69 1481.96,960.87 1495.96,974.88 1573.81,974.88 1595.67,953.01 U8.1@1595.67,939.69 ; U14.1@1707.1,939.69 1707.99,940.58 1707.12,941.46 v2(1707.12,969.39) ; C20.2@2024.66,757.66 2025.99,758.99 2064.99,758.99 v2(2067.28,761.28) ; v2(2622.73,945.03) 2623.06,944.69 U2.1@2643.62,944.69 ; v2(2736,944.9) 2736.21,944.69 U1.1@2755.05,944.69 ; v3(2857.01,904.02) 2866.47,913.48 U5.1@2866.47,944.69 2865.58,943.8 U5.1@2865.8,943.58 ; v2(2959,718) U17.3@2959,783 2963.01,787.01 2963.01,864.25 v2(2963.87,865.11) ; 2971.76,873 C17.2@3003,873 ; R34.2@2994,463 3009,478 v2(3009,498) U17.7@3009,553 3009,613 3019,623 3049,623 3059,613 U17.8@3059,553
  Top Layer w15: LED1.1@1540.02,-165.82 1547.48,-165.82 1547.48,-165.34 1556.14,-156.68 1575.03,-156.68 1598.3,-133.41 1667.8,-133.41 ; v2(2963.87,865.11) 2971.76,873 2977.9,879.14 U10.1@2977.9,944.69 ; R15.2@3022.76,168.85 3022.76,202.97 v1(3035.66,215.86)
  Top Layer w20: v2@2408.87,260.59 C19.2@2446.87,260.59
  Bottom Layer w6: 2447.34,267.83 2452.34,262.83
  Bottom Layer w12: v2(2067.28,761.28) 2535.72,761.28 2579,718 ; v2(2579,608) 2579,713 ; v2(3009,498) 3038.65,498
  Bottom Layer w15: C9.2@1527.64,962.34 1700.07,962.34 v2(1707.12,969.39) 1710.92,965.6 1776.3,965.6 C10.2@1783,958.9 1783,967.47 v2(1799.16,983.63) v2@1797.56,985.22 ; v2(2622.73,945.03) 2816,945.03 v3(2857.01,904.02) 2864.73,896.3 C8.2@2902.9,896.3 ; C8.2@2912.32,886.88 2942.1,886.88 v2(2963.87,865.11)
  Bottom Layer w20: v3(1481.35,906.66) 1478.47,909.55 1478.47,926.12 C9.2@1511.25,958.9 ; C9.2@1524.2,958.9 1503.4,958.9 ; C9.2@1524.2,967.2 1511.7,967.2 1503.4,958.9 ; 1759.3,-130.75 1641.88,-248.16 1439.69,-248.16 1376,-184.47 1376,892.68 1442.22,958.9 1503.4,958.9 ; v2(2405.39,261) 2445.65,261 2450.74,261 C22.2@2450.74,208.58
  Bottom Layer w30: v4(1679,-72) 1679.96,-72.96 1679.96,-97.09 1713.61,-130.75 1759.3,-130.75 1956.14,-130.75 2017.2,-69.68 2469.96,-69.68 ; v2@2405.65,258.41 2445.65,258.41 2445.65,261 R35.2@2445.65,318.41 ; C22.2@2450.74,208.58 2450.74,183.19 2478.93,155 2523.4,155 2574,104.4 CN2.2@2574,90 2574,-67 ; v4(2469,-132) 2469.96,-131.04 2469.96,-69.68 ; 2579,718 v2(2959,718) 2992.96,718 3035.38,675.58 3035.38,-6.36 2974.74,-67 2574,-67 ; 2469.96,-69.68 2469.96,-67 2574,-67
3V3_USB_PYLK: C6.2 JP1.1 U13.1 | length 2404.2
  Top Layer w20: v7@1599.8,-197 1644.03,-241.23 v7(1734.96,-241.23)
  Bottom Layer w20: v7(1599,-197) 1599,-191.59 1589.27,-181.86 1589.27,-176.02 1454.1,-40.84 1454.1,618.86 1529.6,694.36 1728.6,694.36 1772.24,738 1774,738 1787.24,751.24 JP1.1@1787.24,753 ; v7(1734.96,-241.23) 1741.82,-248.09 2592.91,-248.09 v4(2679,-162) v4@2680.78,-163.78
5V: D1.1 D2.1 FUSE2.1 JP3.3 | length 529.6
  Bottom Layer w20: D1.1@2100,2970 2091.37,2978.63 2091.37,3112.11 2118.13,3138.86 2144.77,3138.86 2164,3158.1 FUSE2.1@2164,3179.39 2166.61,3182 D2.1@2295,3182 2295,3128 JP3.3@2355,3068
5V_OUT_EN: R28.1 U15.11 | length 1053.8
  Top Layer w6: R28.1@1489,258 1489,283 1539.65,333.65 1798.42,333.65 1909.92,445.16 v2(1909.92,451.42) ; v2(2310.76,591.53) 2310.8,591.58 U15.11@2386.32,591.58
  Bottom Layer w6: v2(1909.92,451.42) 2110.42,451.42 2250.53,591.53 v2(2310.76,591.53)
5V_USB_CHGR: 5V_USB_CHGR.1 C3.2 C4.2 FUSE1.2 U9.3 U16.5 | length 748.2
  Top Layer w20: 5V_USB_CHGR.1@1462,330 1462,327.29 1438.4,303.69 1438.4,171.1 1466.5,143 U16.5@1466.5,136.09 ; U16.5@1466.5,128 U16.5@1466.5,136.09 ; v6(1494,138) 1492.09,136.09 U16.5@1466.5,136.09
  Bottom Layer w30: v6(1494,138) 1504.39,148.39 FUSE1.2@1777.02,148.39 1777.02,-32.63 1759,-50.65 v4(1759,-52) v4@1758.04,-51.04
5V_USB_PYLK: C15.2 D1.2 JP1.3 U16.1 | length 4199
  Top Layer w20: v4(1413,860) 1413,864.06 1402.1,874.96 1402.1,1089.24 v4(1530,1217.14) 1529.89,1217.25 1529.89,1330.87 1634.57,1435.55 v4(1974.71,1435.55) ; v6(1431.39,-80.18) 1432.3,-81.09 1478.09,-81.09 C15.2@1479,-82 ; U16.1@1466.5,27.69 1466.5,13 1466.19,12.69 1466.19,-67 C15.2@1479,-67 ; v4(2081,1537) v4@2174,1537
  Bottom Layer w20: v4(1413,860) 1462.03,810.97 1462.03,692 ; v6(1431.39,-80.18) 1428.92,-79.68 1425.21,-75.97 1423.81,-74.57 1414.92,-61.23 1414.92,644.89 1462.03,692 ; JP1.3@1589,753 1585.18,756.82 1526.85,756.82 1462.03,692 ; v4(1974.71,1435.55) 1984.58,1435.55 2073.5,1524.48 2073.5,1525.44 v4@2083.24,1535.18 ; D1.2@2006.5,2970 2006.5,2793.28 1840.99,2627.77 1840.99,2202.59 2168.73,1874.84 2168.73,1556.33 2182,1543.06 v4(2182,1539)
5V_USB_START: 5V_USB_STK.1 D2.2 U21.A4 U21.A9 U21.B4 U21.B9 | length 703.7
  Top Layer w10: v4(2323.79,3273.1) 2356.63,3240.26 2483.26,3240.26 5V_USB_STK.1@2488,3245 ; v4@2323.79,3274.66 2358.19,3240.26
  Top Layer w15: U21.B9@2322.98,3334.13 U21.B9@2322.98,3352.12
  Top Layer w20: U21.A9@2133.8,3351.74 2133.8,3274.04 v4(2134.45,3273.39) ; v4@2322.98,3273.91 U21.B9@2322.98,3334.13
  Bottom Layer w20: v4(2134.45,3273.39) 2144.87,3262.98 2313.67,3262.98 v4(2323.79,3273.1) 2328.34,3273.1 2388.5,3212.94 D2.2@2388.5,3182
AD_TVDD: R16.1 R20.2 U15.19 | length 586.3
  Top Layer w6: R20.2@1755.52,556.7 R16.1@1755.52,605.61 1812.79,605.61 1877.97,670.79 2053.66,670.79 2097.59,626.86 2200.86,626.86 2209.16,635.17 U15.19@2209.16,670.32
BOOT0: CN5.5 R41.2 U18.60 | length 1046.2
  Top Layer w8: CN5.5@1525,1717 1533.48,1725.48 1562.04,1725.48 1777.71,1941.15 1777.71,2232.36 1933.45,2388.1 U18.60@2027.63,2388.1
  Bottom Layer w10: CN5.5@1525,1717 R41.2@1620,1717
DIR_RESET: U10.5 U15.3 | length 1394.4
  Top Layer w5: U15.3@2386.32,434.1 2474.66,434.1 2514.03,394.73 2579.22,329.55 2579.22,305.77 2651.78,233.22 2802.12,233.22 2858.53,289.63 2858.53,797.04 2950.97,889.47 2950.97,961.45 2999.1,1009.59 2999.1,1026.92 U10.5@3003.49,1031.31
DIR_RTCK_DTR: U5.5 U15.4 | length 1362.6
  Top Layer w5: U15.4@2386.32,453.79 2477.69,453.79 2517.06,414.42 2597.43,334.05 2597.43,307.49 2653.09,251.83 2789.95,251.83 2842.53,304.41 2842.53,801.32 2937.97,896.76 2937.97,968.09 2896.45,1009.6 2896.45,1026.92 U5.5@2892.06,1031.31
DIR_TCK_SWCLK: U2.5 U15.21 | length 808
  Top Layer w5: v2(2146.12,813.67) 2169.79,790 U15.21@2169.79,670.32 ; v3(2227.49,847.13) 2227.49,848.57 2271.33,892.41 2456.34,892.41 2570.71,1006.79 2627.38,1063.46 2661.19,1063.46 2669.21,1055.43 U2.5@2669.21,1031.31
  Bottom Layer w5: v2(2146.12,813.67) 2163.61,831.16 2211.52,831.16 v3(2227.49,847.13)
DIR_TDI_VCP_TX: U12.5 U15.20 | length 603.7
  Top Layer w6: U12.5@1844.12,1026.31 1844.12,991.77 1857.92,977.98 1874.97,977.98 1917.25,935.7 1917.25,912.92 1986.11,844.06 2147.64,844.06 2189.47,802.24 U15.20@2189.47,670.32
DIR_TDO_SWO: U7.5 U15.43 | length 1242.4
  Top Layer w6: U7.5@1507.55,1026.31 1507.55,1007.73 1493.94,994.13 1480.97,994.13 1456.14,969.3 1456.14,899.38 1541.99,813.52 1557.93,813.52 v3(1560.55,810.9) ; v2(2104,548) 2129.69,548 2228.84,448.85 U15.43@2228.84,335.68
  Bottom Layer w5: v3(1560.55,810.9) 1565.05,815.41 1854.21,815.41 2100.36,569.25 2100.36,551.64 v2(2104,548)
DIR_TMS_SWDIO: U1.5 U15.14 | length 784.3
  Top Layer w6: U15.14@2307.58,670.32 2307.58,696.99 2310.95,700.36 2310.95,701.29 2320.51,710.85 2321.44,710.85 2440.13,829.54 2735.8,829.54 2833.4,927.13 2833.4,966.36 2814.78,984.98 2797.79,984.98 2782.52,1000.25 2782.52,1029.42 U1.5@2780.64,1031.31
DIR_TRST_RTS: U8.5 U15.2 | length 1100.7
  Top Layer w6: U8.5@1621.26,1026.31 1621.85,1025.72 1621.85,997.24 1636.53,982.56 1662.14,982.56 1677.94,966.76 1677.94,876.79 v2(1702.06,852.67) ; v2(2155.52,574.68) 2184.72,574.68 2344.98,414.42 U15.2@2386.32,414.42
  Bottom Layer w5: v2(1702.06,852.67) 1710.33,844.41 1907.59,844.41 2155.52,596.48 v2(2155.52,574.68)
DIR_VCP_RX: U14.5 U15.22 | length 688.5
  Top Layer w6: U14.5@1732.69,1026.31 1734.07,1024.93 1734.07,1000.14 1750.6,983.6 1758.2,983.6 1784,957.81 1784,863.06 1798.61,848.45 1953.3,848.45 1976.05,825.71 2086.18,825.71 2130.38,781.51 2150.1,761.79 U15.22@2150.1,670.32
F_VDD: C31.2 R44.2 R45.2 U19.3 U19.7 U19.8 | length 863
  Bottom Layer w10: U19.7@1800,1677 1775,1677 U19.8@1750,1677 1755.06,1671.94 1755.06,1581.79 C31.2@1768.78,1568.07 1770.28,1566.57 1831.72,1566.57 1842.25,1577.1 1842.25,1589.25 1853.68,1600.68 1934.04,1600.68 1985,1651.65 1985,1769 1908,1846 1871,1846 1852.68,1864.32 1852.68,1904.32 U19.3@1850,1907 1850,1982.27 R45.2@1829.57,2002.7
GND: C1.1 C2.1 C3.1 C4.1 C5.1 C6.1 C7.1 C8.1 C9.1 C10.1 C11.1 C12.1 C13.1 C14.1 C15.1 C16.1 C17.1 C18.1 C19.1 C20.1 C21.1 C22.1 C23.1 C24.1 C25.1 C26.2 C27.1 C28.2 C29.1 C31.1 C32.1 C33.1 C34.1 C35.1 C36.1 C37.1 C38.1 C39.1 C40.1 C41.1 CN1.5 CN2.4 CN3.3 CN4.31 CN5.2 J1.3 K1.1 K3.2 LED2_VDD*.2 Q1.2 R1.1 R3.2 R7.2 R19.1 R20.1 R24.1 R27.2 R29.1 R32.2 R54.1 R55.2 R56.1 R57.1 R60.2 U1.2 U2.2 U3.2 U4.2 U5.2 U6.2 U7.2 U8.2 U9.1 U10.2 U11.2 U12.2 U13.2 U14.2 U15.8 U15.23 U15.47 U16.2 U17.4 U18.31 U18.63 U19.4 U20.2 U21.A1 U21.A12 U21.B1 U21.B12 U22.2 U23.1 USB1.A1 USB1.A12 USB1.B1 USB1.B12 Y1.2 Y1.4 Y2.2 Y2.4 | length 5655.2
  Top Layer w6: v2(2849,988) 2879,988 2892.06,974.94 U5.2@2892.06,944.69 ; U11.2@2934.2,65.5 U11.2@2936.7,63
  Top Layer w10: CN5.2@1425,1517 1425,1520.92 1472.41,1568.33 1558.24,1568.33 1832,1842.09 1832,2203.26 1957.79,2329.05 U18.63@2027.63,2329.05 ; U7.2@1507.55,939.69 1508.54,938.7 1508.54,903.08 1513.36,898.25 ; R29.1@1549,258 1554,263 v2(1554,293) ; C15.1@1564,-67 1564,-77 C15.1@1569,-82 ; v2(1609,887.6) 1619.89,898.49 1619.89,938.32 U8.2@1621.26,939.69 ; C1.1@1619,98 C1.1@1624,103 ; C2.1@1689,59 C2.1@1690,58 ; R7.2@1719,258 v2@1807.95,258 ; v2(1726.9,878.7) 1732.59,884.39 U14.2@1732.59,939.59 ; R19.1@1755.52,458.88 R19.1@1757.04,460.4 ; v2(1807.1,257.15) v2@1807.95,258 ; R3.2@1834,258 v2@1807.95,258 ; U12.2@1844.12,939.69 1845.41,938.4 1845.41,895.62 1855.83,885.2 1855.83,879.83 v2@1854,878 ; C20.1@1947.36,743 1957.36,753 C20.1@1958,753 1951.95,759.05 1951.95,777.14 1973.23,798.42 2075.98,798.42 2110.82,763.58 ; C16.1@1982.59,232.5 C16.1@1983.59,233.5 ; USB1.A1@2097.31,32.89 USB1.B12@2109.12,32.89 ; USB1.B1@2349.28,32.89 USB1.A12@2361.09,32.89 ; v2@2393.47,336.56 v2@2393.6,336.69 ; v2@2395.61,337.02 2413.36,337.02 2442.57,307.8 2491.07,307.8 2508.91,289.95 C19.1@2508.87,260.59 ; U2.2@2668.26,943.75 2671.1,946.58 2671.1,965.95 2688.15,983 v2@2724.02,983 ; v2(2723.2,980.6) 2724.02,981.42 v2@2724.02,983 ; U1.2@2780.64,944.69 2778.75,946.58 2778.75,968.25 2764,983 v2@2724.02,983 ; U10.2@3003.49,944.69 3005.38,942.8 3005.38,916.96 3017.61,904.72 3064.04,904.72 ; CN4.31@3053.58,3017 CN4.31@3060,3017
  Top Layer w11: 2110.82,763.58 2130.42,743.98 U15.23@2130.42,670.32 ; U15.47@2307.58,335.68 2307.58,378.91 2313.74,385.07 2336.08,385.07 2381.87,339.28 v2(2393.35,339.28) ; U15.8@2386.32,532.53 2553.94,532.53 2575.47,511 C21.1@2579.12,511
  Top Layer w12: Q1.2@1404.2,732.8 Q1.2@1409.01,727.99 ; v2(2915.71,677.27) 2920.84,677.27 2909,689.11 2909,811.88 2933.39,836.27 v2(2933.39,836.51) ; v2@3060.2,923 3061.67,921.53 3061.67,909.53 3064.04,907.16 3064.04,904.72 3064.04,873.96 C17.1@3065,873
  Top Layer w15: U16.2@1503.48,27.48 1504.91,26.04 1504.91,-7.91 C15.1@1564,-67 ; C15.1@1569,-82 v2(1626.56,-82) ; U6.2@1824.66,33.05 1826.24,31.47 1827.29,32.52 v2(1852.08,32.52) ; v2(2564,-127) U13.2@2614,-127 2616.16,-124.84 2648.66,-124.84 2662.23,-111.26 v2@2708.26,-111.26 ; v2(2709,-112) 2709,-67.56 2720.26,-56.3 K1.1@2730.55,-56.3
  Top Layer w20: C15.1@1564,-67 v2(1564,-32) ; C1.1@1624,103 v2(1664,103) ; v2(1663.83,555.29) 1664.59,556.04 1695.17,556.04 R20.1@1695.93,556.8 ; C2.1@1690,58 v2(1719,58) ; R19.1@1757.04,460.4 1757.04,460.12 1761.52,455.64 1783.94,455.64 v2(1784.7,454.87) ; v4(2066.08,88) 2069.03,88 USB1.A1@2103.17,53.85 ; v1@2068.38,3297.68 v1(2067.61,3296.91) 2067.61,3297.42 2104.89,3334.7 U21.B1@2104.89,3335.54 ; CN1.5@2269,1103 CN1.5@2276.47,1110.47 ; USB1.B1@2353.5,52.28 v4@2373.66,72.44 ; U21.B12@2354.92,3343.23 2354.92,3312.23 2379.91,3287.25 v1@2399.37,3287.25 ; C21.1@2574.12,520 2579.12,515 C21.1@2579.12,511 2579.41,511.28 2612.41,511.28 2624.12,523 v2(2624.12,590.57) 2647.95,614.41 2724.41,614.41 v2(2730.26,608.55) 2731.35,608.55 2734.45,611.65 2790.47,611.65 v2(2801.03,601.1) 2811.58,590.54 v2(2811.58,526.85) 2811.58,463.13 2811.58,315.46 v2(2789.12,293) 2773.85,277.73 2703.89,277.73 v2@2693.64,287.98 ; v2(2627.98,405.29) 2655.06,405.29 Y1.2@2670.66,389.69 2672.39,387.96 2672.39,314.73 C18.1@2674.12,313 2678.12,313 2683.12,308 2683.12,298.5 2684.37,297.25 ; 2684.37,293.63 v2(2691.83,286.18) ; C24.1@2736.12,563 2736.85,562.27 2736.85,477.04 Y1.4@2737.59,476.31 2750.74,463.16 v2(2811.55,463.16)
  Bottom Layer w6: v2@1853.26,880.83 v2(1856.89,880.83)
  Bottom Layer w10: v2(1856.89,880.83) 1856.89,962.49 1926.46,1032.06 1969.72,1032.06 1992,1009.78 1992,938.79 2019.89,910.9 v2(2019.89,908.89) ; v2@2019,906 2037.72,887.28 2104.81,887.28 U3.2@2105.54,888
  Bottom Layer w20: CN1.5@2269,1103 2275,1109 2275,1360.82 CN3.3@2273.26,1362.56 ; CN3.3@2275,1362.56 CN3.3@2275,1365.94
  other v1: 1400,1342 1475,1342 2850,1342 2925,1342 3000,1342 3075,1342 1400,1442 3075,1442 2417,1497 2838,1502 2505,1504 2675,1505 2245,1516 1705.66,1517.81 2639,1527 2885,1527 1595,1606 2217,1617 2052,1635 2326.75,1648.33 2527.82,1650.27 2215,1668 2575.53,1695.33 2214,1704 2049,1715 2304.96,1739.31 2571.69,1767 2225,1774 2659.54,1776.12 2495.7,1819.74 2348,1821 2608.98,1821.91 2556.24,1875.83 1998,1888 2255,1910 2516.21,1924.73 2254,1944 1907.13,1971.78 1936,1982 2229.03,1983.45 2196,2028 2114,2037 1851,2072 2065,2115 1933.13,2237.18 1952.2,2265.65 2100.18,2347.19 2105.33,2395.01 2100.19,2443.42 2419.73,2454.31 2097.46,2519.66 2399.09,2535.03 2125.91,2584.73 2349,2617 2247,2619 2647.71,2702.48 2644.7,2743.09 1644.25,3060.62 1400,3092 2950,3092 3075,3092 2775,3117 1475.48,3140.55 1581.68,3146.33 1400,3167 3075,3167 1400,3242 3075,3242 2401.47,3287.7 1789.05,3290.68 1844.5,3301.16 1400,3317 2650,3317 3075,3317 1500,3342 1650,3342 1786.31,3341.63 1975,3342 2947.7,3421.05 2807.18,3424.94 1961.72,3466.9 2095.01,3472.73 2364.66,3474.7 1400,3517 1500,3517 1600,3517 1700,3517 2775,3517 2875,3517 2975,3517 3075,3517 1959.9,3534.85 2199.56,3574.55 2261.62,3576.07 2547.86,3588.04
  other v2: 2119,-207 2221.5,-207 2324,-207 2454,-207 2816.25,-204 2874,-204 3084,-197 2449,-182 3084,-137 2864,-127 2914,-127 2129,-112 2219,-112 2324,-112 3032.49,-98.38 2914,8 2820.04,10.77 2668.39,15.36 1504,78 2989,298 2989,363 1519,373 1564,373 2814.12,383 1411.3,698.34 1414,758 2536.35,890.57 3069,923 2595.94,987.95 2639,1203 2734,1203 2849,1203 3084,1203 1389,1208
  other v3: 1854.23,-204.27 1928.48,-204.28 1955.46,199.73 1954.2,251.2 2577.05,250.77 1593.93,301.18 2058.43,344.59 2187.63,406.94 2122.47,407.5 1799.71,646.68 2885.33,677.53 2951.76,681.38 1818.86,690.62 2217.55,724.58 2667.59,756.06 2722.58,756.45 2610.66,756.84 2775.24,757.63 2884.67,758.55 1638,785 1549,862 2589.29,903.47 2581.19,941.9 3065.69,952.78 3067.32,983.65 2540.59,1134.54 1383.3,1157.1 2230.13,1215.83 2332.35,1216.38 2275.13,1232.49
  other v4: 2376.74,72.19
L_USB_CN_DM: U6.4 USB1.A7 USB1.B7 | length 509.2
  Top Layer w6: U6.4@1922.15,-4.4 1923.18,-5.43 1923.18,-22.54 1950.04,-49.4 2170.36,-49.4 2199.49,-20.27 USB1.B7@2199.49,32.71 ; USB1.B7@2199.67,32.89 2199.7,78.7 2209,88 2229,88 2239,78 USB1.A7@2239,32.93
L_USB_CN_DP: U6.6 USB1.A6 USB1.B6 | length 673
  Top Layer w6: U6.6@1922.15,70.4 1921.26,69.51 1894.39,69.51 1884.35,59.47 1884.35,-36.6 1917.22,-69.47 2176.27,-69.47 2216.55,-29.19 2218.95,-26.79 ; 2219.1,-27.26 USB1.A6@2219.1,32.64 ; 2219.75,-32.39 2219.75,-29.19 ; 2220.31,-32.96 2224.05,-36.69 2253.06,-36.69 2258.31,-31.44 USB1.B6@2258.31,32.48
LED_BLUE: R8.2 U15.28 | length 674.3
  Top Layer w6: R8.2@1574,433 1607.51,433 1684.7,355.81 1793.56,355.81 1875.33,437.58 1875.33,550.41 1897.92,573 1929,573 1949.79,552.21 U15.28@2051.68,552.21
LED_GREEN: R5.2 U15.26 | length 726.2
  Top Layer w6: R5.2@1574,543 1587,530 1591.4,530 1653.27,468.13 1653.27,442.27 1690.41,405.13 1786.27,405.13 1837.48,456.34 1837.48,571.48 1895.75,629.75 1945.91,629.75 1984.07,591.58 U15.26@2051.68,591.58
LED_RED: R4.2 U15.27 | length 697.6
  Top Layer w6: R4.2@1574,488 1575.4,486.6 1595.49,486.6 1632.6,449.48 1632.6,434.05 1685.22,381.43 1790.52,381.43 1856.68,447.59 1856.68,560.68 1894,598 1944,598 1970.1,571.9 U15.27@2051.68,571.9
NetC16_2: C16.2 R30.2 | length 64.1
  Top Layer w6: 2040.21,294.75 2040.21,236.88 C16.2@2044.59,232.5
NetC25_2: C25.2 R36.1 Y2.3 | length 268.9
  Top Layer w8: 2354,1868 2366,1856 2366,1844.37 2397.44,1812.93 2397.44,1728.44 2387.16,1718.16 2374.31,1718.16 Y2.3@2354.69,1698.53 ; C25.2@2372,1625 Y2.3@2372,1681.22
NetC27_2: C27.2 R40.1 Y2.1 | length 200.2
  Top Layer w8: 2404,1868 2404,1842.89 2436.6,1810.29 2436.6,1770.18 Y2.1@2441.31,1765.47 2497.53,1765.47 C27.2@2523.53,1765.47
NetC28_1: C28.1 R42.2 Y3.2 | length 212.9
  Top Layer w8: C28.1@2096,1700 2107.56,1711.56 2107.56,1740.46 2079.81,1768.21 Y3.2@2079.81,1781 2079.81,1793.8 2101.75,1815.75 2101.75,1866 ; 2100.84,1868.75 2103.15,1878.46 2103.15,1870.6 2105.75,1868
NetC29_2: C29.2 R43.2 Y3.1 | length 231
  Top Layer w8: 2145.24,1874.18 2149.53,1878.47 ; 2154,1868 2154,1874 2165.2,1862.8 2161.56,1859.16 ; 2161,1866 2161,1862.51 2154.97,1856.48 2154.97,1815.16 2159.65,1810.47 2163.53,1810.47 2171,1803 Y3.1@2171,1775 ; C29.2@2172,1700 2158.5,1713.5 2158.5,1746.51 2180.2,1768.21 Y3.1@2180.2,1781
